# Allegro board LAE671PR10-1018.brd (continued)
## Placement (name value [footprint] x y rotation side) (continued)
CT32  0.1U_0201_6.3V6K  [C_0201]  30.03 44.23 0 bottom
CT33  0.1U_0201_6.3V6K  [C_0201]  30.03 42.7 0 bottom
CT34  0.1U_0201_6.3V6K  [C_0201]  30.03 43.34 0 bottom
CT35  0.1U_0201_6.3V6K  [C_0201]  31.79 50.88 0 bottom
CT36  0.1U_0201_6.3V6K  [C_0201]  31.79 50.25 0 bottom
CT37  27P_0201_25V8  [C_0201]  16.69 38.5 270 bottom
CT38  27P_0201_25V8  [C_0201]  16.7 39.12 90 bottom
CT39  0.22U_0201_6.3V6M  [C_0201]  15.57 45.68 180 bottom
CT40  0.22U_0201_6.3V6M  [C_0201]  13.2 49.91 135 bottom
CT41  0.22U_0201_6.3V6M  [C_0201]  15.57 45.04 180 bottom
CT42  0.22U_0201_6.3V6M  [C_0201]  12.77 49.44 135 bottom
CT43  0.22U_0201_6.3V6M  [C_0201]  15.83 43.5 180 bottom
CT44  0.22U_0201_6.3V6M  [C_0201]  11.98 48.29 135 bottom
CT45  0.22U_0201_6.3V6M  [C_0201]  15.83 44.14 180 bottom
CT46  0.22U_0201_6.3V6M  [C_0201]  12.37 48.69 135 bottom
CT47  0.1U_0201_6.3V6K  [C_0201]  31.79 44.41 0 bottom
CT48  0.1U_0201_6.3V6K  [C_0201]  30.01 41.99 0 bottom
CT49  0.1U_0201_6.3V6K  [C_0201]  31.79 43.77 0 bottom
CT50  0.1U_0201_6.3V6K  [C_0201]  30.01 41.36 0 bottom
CT51  0.1U_0201_6.3V6K  [C_0201]  15.88 64.15 45 top
CT52  1U_0201_6.3V6M  [C_0201]  26.11 48.52 0 top
CT53  1U_0201_6.3V6M  [C_0201]  26.11 47.93 0 top
CT54  1U_0201_6.3V6M  [C_0201]  22.8 47.73 270 top
CT55  1U_0201_6.3V6M  [C_0201]  23.03 50.38 0 top
CT56  1U_0201_6.3V6M  [C_0201]  26.11 46.67 0 top
CT57  1U_0201_6.3V6M  [C_0201]  26.11 47.3 0 top
CT58  1U_0201_6.3V6M  [C_0201]  25.48 46.64 270 top
CT59  0.1U_0201_10V6K  [C_0201]  25.56 50.55 0 top
CT60  1U_0201_6.3V6M  [C_0201]  21.46 51.42 0 top
CT61  1U_0201_6.3V6M  [C_0201]  16.42 52.19 270 bottom
CT62  10U_0402_6.3V6M  [C_0402]  16.42 52.97 90 bottom
CT63  10U_0402_6.3V6M  [C_0402]  15.46 53.18 90 bottom
CT64  10U_0402_6.3V6M  [C_0402]  14.59 53.18 90 bottom
CT65  10U_0402_6.3V6M  [C_0402]  13.71 53.17 90 bottom
CT66  1U_0201_6.3V6M  [C_0201]  24.88 44.28 0 top
CT67  1U_0201_6.3V6M  [C_0201]  22.97 43.44 0 top
CT68  1U_0201_6.3V6M  [C_0201]  22.97 44.02 0 top
CT69  1U_0201_6.3V6M  [C_0201]  22.36 43.44 180 top
CT70  1U_0201_6.3V6M  [C_0201]  22.36 44.02 180 top
CT71  1U_0201_6.3V6M  [C_0201]  24.88 43.69 0 top
CT72  1U_0201_6.3V6M  [C_0201]  20.87 46.57 0 top
CT73  1U_0201_6.3V6M  [C_0201]  19.64 46.29 270 top
CT74  1U_0201_6.3V6M  [C_0201]  23.4 48.53 0 top
CT75  1U_0201_6.3V6M  [C_0201]  18.96 47.92 90 top
CT76  1U_0201_6.3V6M  [C_0201]  23.39 47.93 0 top
CT77  1U_0201_6.3V6M  [C_0201]  19.05 46.3 270 top
CT78  1U_0201_6.3V6M  [C_0201]  18.46 46.3 270 top
CT79  47U_0603_6.3V  [C_0603]  15.6 56.85 180 bottom
CT80  47U_0603_6.3V  [C_0603]  15.6 55.58 180 bottom
CT81  47U_0603_6.3V  [C_0603]  15.6 58.12 180 bottom
CT82  1U_0201_6.3V6M  [C_0201]  24.96 49.79 0 top
CT83  1U_0201_6.3V6M  [C_0201]  24.3 49.19 90 top
CT84  1U_0201_6.3V6M  [C_0201]  24.68 47.89 90 top
CT85  10U_0402_6.3V6M  [C_0402]  18.69 43.67 270 top
CT86  10U_0402_6.3V6M  [C_0402]  19.57 43.67 270 top
CT87  1U_0201_6.3V6M  [C_0201]  19.72 44.41 180 top
CT88  1U_0201_6.3V6M  [C_0201]  19.72 45.04 180 top
CT89  1U_0201_6.3V6M  [C_0201]  22.26 44.66 180 top
CT90  1U_0201_6.3V6M  [C_0201]  20.99 44.66 180 top
CT91  1U_0201_6.3V6M  [C_0201]  24.68 47.11 270 top
CT92  47U_0603_6.3V  [C_0603]  26.73 58.04 180 bottom
CT93  47U_0603_6.3V  [C_0603]  26.73 56.82 180 bottom
CT94  4.7U_0402_6.3V6M  [C_0402]  15.13 35.12 90 top
CT95  4.7U_0402_6.3V6M  [C_0402]  22.98 33.46 0 top
CT96  2.2U_0402_6.3V6M  [C_0402]  20.44 34.88 90 top
CT97  4.7U_0402_6.3V6M  [C_0402]  27.68 37.43 90 top
CT98  4.7U_0402_6.3V6M  [C_0402]  34.94 37.05 0 top
CT99  2.2U_0402_6.3V6M  [C_0402]  32.98 37.12 90 top
CT100  4.7U_0402_6.3V6M  [C_0402]  283.17 21.04 0 bottom
CT101  4.7U_0402_6.3V6M  [C_0402]  294.58 13.71 0 bottom
CT102  2.2U_0402_6.3V6M  [C_0402]  283.17 14.93 180 bottom
CT103  10U_0603_25V6M  [C_0603]  8.88 40.11 270 top
CT104  10U_0603_25V6M  [C_0603]  12.49 61 270 top
CT105  1U_0402_25V6K  [C_0402]  287.05 48.27 90 bottom
CZ1  0.1U_0402_10V7K  [C_0402]  138.33 72.34 0 top
CZ2  1U_0402_6.3V6K  [C_0402]  140.43 72.35 0 top
CZ3  1U_0402_6.3V6K  [C_0402]  145.96 12.83 90 bottom
CZ4  0.1U_0402_10V7K  [C_0402]  150.37 10.95 90 bottom
CZ5  0.1U_0402_10V7K  [C_0402]  148.07 15.01 180 bottom
CZ6  0.1U_0402_10V7K  [C_0402]  125.2 41.34 270 top
CZ7  1U_0402_6.3V6K  [C_0402]  120.05 38.74 90 top
CZ8  0.1U_0402_10V7K  [C_0402]  128.31 69.68 180 top
CZ9  1U_0402_6.3V6K  [C_0402]  125.64 69.68 0 top
D2  -  [TVNST52302AB0_SOT523-3]  284.47 22.97 90 bottom
D3  -  [AZ5B25-01F_DFN0603P2Y2]  285.4 23.38 270 bottom
D4  -  [AZ5B25-01F_DFN0603P2Y2]  285.4 24.08 90 bottom
D5  -  [BAT54CW_SOT323-3]  42.01 52.03 90 bottom
D6  -  [BAT54CW_SOT323-3]  57.32 67.83 270 bottom
D7  -  [RB751V40_SC76-2]  267.86 64.74 0 top
D8  -  [RB751V40_SC76-2]  267.86 66.43 0 top
D9  -  [RB751V40_SC76-2]  271.41 64.57 90 top
D10  -  [TVNST52302AB0_SOT523-3]  272.25 57.17 180 top
D11  -  [RB751V40_SC76-2]  254.22 8.97 90 bottom
D12  -  [RB751V40_SC76-2]  201.23 7.35 90 bottom
D13  -  [BAT54CW_SOT323-3]  38.71 52.28 90 bottom
D18  AZ5B25-01F_DFN0603P2Y2  [ESD101-B1-02ELS_TSSLP-2-4-2]  49.98 58.99 0 bottom
D20  -  [TVNST52302AB0_SOT523-3]  280.52 8.97 90 bottom
D21  BAT54LPS-7  [BZT52C15LP-7_DFN1006-2-2]  13.97 22.74 180 top
D22  BAT54LPS-7  [BZT52C15LP-7_DFN1006-2-2]  26.17 26.12 180 top
D23  BAT54LPS-7  [BZT52C15LP-7_DFN1006-2-2]  294.49 12.96 180 top
D24  ESD8011MUT5G  [ESD101-B1-02ELS_TSSLP-2-4-2]  8.55 43.52 270 bottom
D25  ESD8011MUT5G  [ESD101-B1-02ELS_TSSLP-2-4-2]  9.64 43.92 225 top
D26  ESD8011MUT5G  [ESD101-B1-02ELS_TSSLP-2-4-2]  8.55 44.15 90 bottom
D27  ESD8011MUT5G  [ESD101-B1-02ELS_TSSLP-2-4-2]  10.09 44.37 45 top
D28  ESD8011MUT5G  [ESD101-B1-02ELS_TSSLP-2-4-2]  7.85 40.22 0 bottom
D29  ESD8011MUT5G  [ESD101-B1-02ELS_TSSLP-2-4-2]  7.51 37.54 0 top
D30  ESD8011MUT5G  [ESD101-B1-02ELS_TSSLP-2-4-2]  7.51 38.3 0 top
D31  ESD8011MUT5G  [ESD101-B1-02ELS_TSSLP-2-4-2]  8.6 37.73 0 top
D32  ESD8011MUT5G  [ESD101-B1-02ELS_TSSLP-2-4-2]  8.55 49.1 270 bottom
D33  ESD8011MUT5G  [ESD101-B1-02ELS_TSSLP-2-4-2]  11.58 47.51 225 top
D34  ESD8011MUT5G  [ESD101-B1-02ELS_TSSLP-2-4-2]  8.55 49.74 90 bottom
D35  ESD8011MUT5G  [ESD101-B1-02ELS_TSSLP-2-4-2]  12.03 47.96 45 top
D36  ESD8011MUT5G  [ESD101-B1-02ELS_TSSLP-2-4-2]  9.92 41.03 180 top
D37  ESD8011MUT5G  [ESD101-B1-02ELS_TSSLP-2-4-2]  9.44 46.71 225 top
D38  ESD8011MUT5G  [ESD101-B1-02ELS_TSSLP-2-4-2]  10.56 41.03 0 top
D39  ESD8011MUT5G  [ESD101-B1-02ELS_TSSLP-2-4-2]  9.89 47.16 45 top
D40  ESD8011MUT5G  [ESD101-B1-02ELS_TSSLP-2-4-2]  8.55 59.96 270 bottom
D41  ESD8011MUT5G  [ESD101-B1-02ELS_TSSLP-2-4-2]  9.13 60.02 225 top
D42  ESD8011MUT5G  [ESD101-B1-02ELS_TSSLP-2-4-2]  8.55 60.6 90 bottom
D43  ESD8011MUT5G  [ESD101-B1-02ELS_TSSLP-2-4-2]  9.67 60.56 45 top
D44  ESD8011MUT5G  [ESD101-B1-02ELS_TSSLP-2-4-2]  8.17 55.65 270 top
D45  ESD8011MUT5G  [ESD101-B1-02ELS_TSSLP-2-4-2]  8.17 57.04 270 top
D46  ESD8011MUT5G  [ESD101-B1-02ELS_TSSLP-2-4-2]  7.41 57.04 270 top
D47  ESD8011MUT5G  [ESD101-B1-02ELS_TSSLP-2-4-2]  10.26 64.35 0 top
D48  ESD8011MUT5G  [ESD101-B1-02ELS_TSSLP-2-4-2]  9.06 65.12 270 bottom
D49  ESD8011MUT5G  [ESD101-B1-02ELS_TSSLP-2-4-2]  12.14 64.69 225 top
D50  ESD8011MUT5G  [ESD101-B1-02ELS_TSSLP-2-4-2]  9.06 65.76 90 bottom
D51  ESD8011MUT5G  [ESD101-B1-02ELS_TSSLP-2-4-2]  12.68 65.23 45 top
D52  ESD8011MUT5G  [ESD101-B1-02ELS_TSSLP-2-4-2]  9.25 56.98 180 top
D53  ESD8011MUT5G  [ESD101-B1-02ELS_TSSLP-2-4-2]  9.56 62.63 270 top
D54  ESD8011MUT5G  [ESD101-B1-02ELS_TSSLP-2-4-2]  9.88 56.98 0 top
D55  ESD8011MUT5G  [ESD101-B1-02ELS_TSSLP-2-4-2]  9.56 63.39 90 top
D56  ESD8011MUT5G  [ESD101-B1-02ELS_TSSLP-2-4-2]  287.12 45.04 0 top
D57  ESD8011MUT5G  [ESD101-B1-02ELS_TSSLP-2-4-2]  288.2 46.95 0 bottom
D58  ESD8011MUT5G  [ESD101-B1-02ELS_TSSLP-2-4-2]  286.49 45.04 180 top
D59  ESD8011MUT5G  [ESD101-B1-02ELS_TSSLP-2-4-2]  287.44 46.95 180 bottom
D60  ESD8011MUT5G  [ESD101-B1-02ELS_TSSLP-2-4-2]  286.45 48.44 180 top
D61  ESD8011MUT5G  [ESD101-B1-02ELS_TSSLP-2-4-2]  277.24 25.48 0 top
D62  ESD8011MUT5G  [ESD101-B1-02ELS_TSSLP-2-4-2]  277.24 26.25 0 top
D63  ESD8011MUT5G  [ESD101-B1-02ELS_TSSLP-2-4-2]  289.55 43.59 180 bottom
D64  ESD8011MUT5G  [ESD101-B1-02ELS_TSSLP-2-4-2]  287.57 52.53 270 top
D65  ESD8011MUT5G  [ESD101-B1-02ELS_TSSLP-2-4-2]  288.51 52.53 270 bottom
D66  ESD8011MUT5G  [ESD101-B1-02ELS_TSSLP-2-4-2]  287.57 53.22 90 top
D67  ESD8011MUT5G  [ESD101-B1-02ELS_TSSLP-2-4-2]  288.51 53.17 90 bottom
D68  ESD8011MUT5G  [ESD101-B1-02ELS_TSSLP-2-4-2]  287.26 49.42 270 top
D69  ESD8011MUT5G  [ESD101-B1-02ELS_TSSLP-2-4-2]  287.26 47.02 270 top
D70  ESD8011MUT5G  [ESD101-B1-02ELS_TSSLP-2-4-2]  287.26 50.06 90 top
D71  ESD8011MUT5G  [ESD101-B1-02ELS_TSSLP-2-4-2]  287.26 47.66 90 top
D72  AZ5B25-01F_DFN0603P2Y2  [ESD101-B1-02ELS_TSSLP-2-4-2]  281.22 23.59 0 bottom
D73  -  [TVNST52302AB0_SOT523-3]  275.3 57.24 180 top
D74  -  [PESD5V0U2BT_SOT23-3]  277.38 39.43 270 bottom
D75  -  [BAT54CW_SOT323-3]  268.4 54.74 180 top
D78  BAT54LPS-7  [BZT52C15LP-7_DFN1006-2-2]  210.29 10.31 90 bottom
D79  BAT54LPS-7  [BZT52C15LP-7_DFN1006-2-2]  263.36 6.55 90 bottom
DA1  -  [ESD203-B1-02EL_TSLP-2-20-2]  283.79 12.2 90 top
DA2  -  [ESD203-B1-02EL_TSLP-2-20-2]  281.85 10.44 90 top
DA3  -  [ESD203-B1-02EL_TSLP-2-20-2]  284.72 7.48 90 top
DA4  -  [ESD203-B1-02EL_TSLP-2-20-2]  280.75 5.08 270 top
DA5  AZ5123-01F.R7G_DFN1006P2X2  [ESD207-B1-02EL_TSLP-2-19-2]  292.71 69.36 90 bottom
DA6  AZ5123-01F.R7G_DFN1006P2X2  [ESD207-B1-02EL_TSLP-2-19-2]  286.55 64.23 270 bottom
DA7  AZ5123-01F.R7G_DFN1006P2X2  [ESD207-B1-02EL_TSLP-2-19-2]  289.38 60.06 270 bottom
DA8  AZ5123-01F.R7G_DFN1006P2X2  [ESD207-B1-02EL_TSLP-2-19-2]  288.33 60.06 270 bottom
DA9  AZ5123-01F.R7G_DFN1006P2X2  [ESD207-B1-02EL_TSLP-2-19-2]  290.51 60.07 270 bottom
DI1  AZ4024-02S_SOT23-3~D  [PESD24VS2UT_SOT23-3]  20.18 25.56 270 bottom
DI2  AZ4024-02S_SOT23-3~D  [PESD24VS2UT_SOT23-3]  26.34 29.41 0 bottom
DI3  AZ4024-02S_SOT23-3~D  [PESD24VS2UT_SOT23-3]  294.02 9.1 0 top
DZ2  -  [RB751V40_SC76-2]  285.79 51.71 90 bottom
DZ3  -  [RB751V40_SC76-2]  289.54 39.72 180 bottom
FD1  FIDUCAL  [FIDUCIAL_C40M80]  294.95 69.36 180 bottom
FD2  FIDUCIAL  [FIDUCIAL_C40M80]  24.26 4.81 180 bottom
FD3  FIDUCAL  [FIDUCIAL_C40M80]  294.34 4.55 0 top
FD4  FIDUCIAL  [FIDUCIAL_C40M80]  17.37 66.29 0 top
H1  H_3P3  [H_3P3-G]  24.62 63.92 180 bottom
H2  H_3P3  [H_3P3-G]  57.63 62.42 180 bottom
H3  H_3P3  [H_3P3-G]  88.73 67.85 180 bottom
H4  H_3P3  [H_3P3-G]  88.73 42.75 180 bottom
H5  H_3P3  [H_3P3-G]  145.73 67.85 180 bottom
H6  H_3P3  [H_3P3-G]  145.73 42.75 180 bottom
H7  H_3P3  [H_3P3-G]  76.76 26.95 180 bottom
H8  H_2P6  [H_2P6-G]  169.58 47.8 180 bottom
H9  H_2P6  [H_2P6-G]  218.19 19.81 180 bottom
H10  H_2P6  [H_2P6-G]  269.95 35.75 180 bottom
H11  H_2P0  [H_2P0-G]  2.63 71.4 0 top
H12  H_2P0  [H_2P0-G]  3.43 38.85 0 top
H13  H_2P0  [H_2P0-G]  3.68 8.8 0 top
H14  -  [H_2P0N]  81.53 74.26 0 top
H16  H_2P0  [H_2P0-G]  294.63 58.25 0 top
H17  H_2P0  [H_2P0-G]  294.11 22.2 0 top
H18  -  [H_2P0N]  148.63 74.26 0 top
H19  H_1P8  [H_1P8-G]  147.57 6.77 0 top
H20  H_1P8  [H_1P8-G]  214.24 8.38 0 top
H21  H_2P0  [H_2P0-G]  3.93 54.94 0 top
H22  -  [H_1P8N]  10.8 66.9 0 top
H23  H_2P0  [H_2P0-G]  293.38 42.15 0 top
H24  -  [CLIP_C6-PM]  167.73 20.5 180 bottom
H25  -  [H_1P2X1P7N]  285.04 66.9 270 bottom
H26  -  [H_1P8X2P3N]  7.49 19.04 0 top
JAPS1  ACES_50506-01841-P01  [ACES_50506-01841-P01_18P]  160.57 27.71 90 top
JAUDIO1  HRS_BM20B(0P8)10DS0P4V(51)  [HRS_BM20B0P810DS0P4V51_10P-T]  291.82 62.6 0 bottom
JCAM1  ACES_50406-02071-001  [ACES_50406-02071-001_20P]  278.8 28.44 270 bottom
JCR1  T-SOL_158-1160902600  [T-SOL_158-1090902600_18P-T]  283.01 34.94 90 top
JDEG1  JXT_FP225H-010G1AM  [JXT_FP225H-010G1AM_10P]  16.3 11.54 0 bottom
JEDP1  EDP  [ACES_50398-04041-001_40P]  51.08 61.8 180 bottom
JESPI1  JXT_FP225H-010G1AM  [JXT_FP225H-010G1AM_10P]  10.77 5.62 90 bottom
JFAN1  ACES_50224-00401-001  [ACES_50224-00401-001_4P]  257.15 5.35 0 bottom
JFAN2  ACES_50224-00401-001  [ACES_50224-00401-001_4P]  204.83 1.82 0 bottom
JFP2  ACES_50521-00841-P01  [ACES_50521-00841-P01_8P-T]  276.08 7.03 180 bottom
JKB1  E-T_6710K-Y15M-31L  [E-T_6710K-Y15M-31L_15P]  21.18 9.59 180 bottom
JNGFF1  LOTES_APCI0146-P004A  [LOTES_APCI0146-P004A_75P]  160.28 17.7 90 bottom
JP2  PAD-OPEN1X1M  [JUMP_43X39]  21.63 23.58 270 top
JP3  PAD-OPEN1X1M  [JUMP_43X39]  23.92 23.53 270 top
JPA1  -  [JUMP_43X39]  278.2 58.55 180 top
JPA2  -  [JUMP_43X39]  288.56 57.73 0 bottom
JRTC1  ACES_50278-00201-001  [ACES_50278-00201-001_2P]  252.88 5.47 90 bottom
JSPI1  ACES_50696-0200M-P01  [ACES_50696-0200M-P01_20P]  163.6 27.28 270 bottom
JSPK1  ACES_50208-00801-003  [ACES_50208-00801-003_8P]  282.76 4.89 270 bottom
JT101  ACES_50278-01201-001  [ACES_50278-01201-001_12P-T]  108.44 14.61 180 bottom
JTAG2  @SHORT PADS~D  [SHORTPADS]  9.09 13.02 180 top
JTP1  ACES_50506-00841-P01  [ACES_50506-00841-P01_8P]  178.58 8.25 180 bottom
JUART1  CVILU_CI1804M1VRA-NH  [CVILU_CI1804M1VRA-NH_4P]  162.79 42.08 270 top
JUSBC1  JAE_DX07SD24JJ3  [JAE_DX07SD24JJ3_24P-T]  7.4 49.34 270 top
JUSBC2  JAE_DX07SD24JJ3  [JAE_DX07SD24JJ3_24P-T]  7.4 65.8 270 top
JUSBC3  JAE_DX07SA24XJ2  [JAE_DX07SA24XJ2_24P-T]  289.2 47.55 90 top
JXDP1  E-T_6601K-Y61N-04L  [E-T_6601K-Y61N-04L_61P]  53.08 73.31 180 top
L1  EXC24CH900U_4P  [INPAQ_MCM1012B900F06BP_4P]  287.61 23.98 180 bottom
L2  EXC24CH900U_4P  [INPAQ_MCM1012B900F06BP_4P]  276.72 35.63 90 bottom
LA1  BLM15PX600SN1D_2P  [MURAT_BLM15PX600SN1D_2P]  274.23 55.75 270 top
LA2  BLM15BB220SN1D_2P  [MURAT_BLM15BB220SN1D_2P]  268.85 62.38 270 bottom
LA3  HCB1005KF-600T25_2P  [TAI-T_HCB1005KF-600T25_2P]  278.64 56.47 180 top
LA4  BLM15BB220SN1D_2P  [MURAT_BLM15BB220SN1D_2P]  273.88 63.89 90 top
LA5  BLM15PX121SN1D_2P  [MURAT_BLM15PX181SN1D_2P]  278.39 11.85 0 top
LA6  BLM15PX121SN1D_2P  [MURAT_BLM15PX181SN1D_2P]  279.26 10.12 0 top
LA7  BLM15PX121SN1D_2P  [MURAT_BLM15PX181SN1D_2P]  279.23 7.68 0 top
LA8  BLM15PX121SN1D_2P  [MURAT_BLM15PX181SN1D_2P]  278.18 5.35 0 top
LA9  BLM15PX330SN1D_2P  [MURAT_BLM15PX330SN1D_2P]  287.36 59.45 180 bottom
LA10  BLM15PX330SN1D_2P  [MURAT_BLM15PX330SN1D_2P]  285.68 61.22 0 bottom
LA11  BLM15PX600SN1D_2P  [MURAT_BLM15PX600SN1D_2P]  266.53 29.2 180 top
LED1  27-11-T1D-CP1Q1RY-3C_WHITE~D  [LED_27-11-T1D-CP1Q1RY-3C_2P]  2.63 27.3 90 top
LED2  27-11-T1D-CP1Q1RY-3C_WHITE~D  [LED_27-11-T1D-CP1Q1RY-3C_2P]  2.63 23.7 90 top
LED3  27-11-T1D-CP1Q1RY-3C_WHITE~D  [LED_27-11-T1D-CP1Q1RY-3C_2P]  2.63 20.1 90 top
LED4  27-11-T1D-CP1Q1RY-3C_WHITE~D  [LED_27-11-T1D-CP1Q1RY-3C_2P]  2.63 16.5 90 top
LED5  27-11-T1D-CP1Q1RY-3C_WHITE~D  [LED_27-11-T1D-CP1Q1RY-3C_2P]  2.63 12.9 90 top
LED6  HT-F196BP5_WHITE  [LED_HT-F196BP5_2P]  290.9 70.69 0 top
LT1  0.60UH +-20% MND-04ABIR60M-XGL  [COILC_XFL4012-601MEC_2P]  18.33 55.36 90 bottom
LT2  LQM18PN1R0MFHD_2P  [CHILI_PBY160808T-300Y-N_2P]  28.19 57.8 270 bottom
LT3  HCB2012KF-121T50_0805  [TAI-T_HCB2012KF-121T50_2P]  15.48 24.66 270 top
LT4  HCB2012KF-121T50_0805  [TAI-T_HCB2012KF-121T50_2P]  29.38 28.26 270 bottom
LT5  HCB2012KF-121T50_0805  [TAI-T_HCB2012KF-121T50_2P]  293.24 15.71 0 top
LT6  HCB2012KF-121T50_0805  [TAI-T_HCB2012KF-121T50_2P]  265.21 4.88 180 bottom
LT7  HCB2012KF-121T50_0805  [TAI-T_HCB2012KF-121T50_2P]  212.34 2.05 180 bottom
MC1  680P_0402_50V7K~D  [C_0402]  55.36 67.12 90 bottom
MD1  -  [PESD5V0U2BT_SOT23-3]  171.26 8.08 270 bottom
MD2  -  [PESD5V0U2BT_SOT23-3]  169.71 2.6 180 bottom
MD3  -  [PESD5V0U2BT_SOT23-3]  272.61 7.28 0 bottom
ML1  EXC24CH900U_4P  [INPAQ_MCM1012B900F06BP_4P]  279.27 12.86 270 bottom
ML2  EXC24CH900U_4P  [INPAQ_MCM1012B900F06BP_4P]  11.19 45.18 135 top
ML3  EXC24CH900U_4P  [INPAQ_MCM1012B900F06BP_4P]  10.14 38.48 90 top
ML4  EXC24CH900U_4P  [INPAQ_MCM1012B900F06BP_4P]  11.74 62.75 180 top
ML5  EXC24CH900U_4P  [INPAQ_MCM1012B900F06BP_4P]  9.34 54.79 90 top
ML6  EXC24CH900U_4P  [INPAQ_MCM1012B900F06BP_4P]  285 50 0 top
ML7  EXC24CH900U_4P  [INPAQ_MCM1012B900F06BP_4P]  284.86 47.42 0 top
NOREF  -  []  145.73 42.75 0 top
NOREF#2  -  []  88.73 67.85 0 top
NOREF#3  -  []  81.65 38.23 270 top
NOREF#4  -  []  81.53 74.26 0 top
NOREF#5  -  []  269.95 35.75 0 top
NOREF#6  -  []  88.73 67.85 0 top
NOREF#7  -  []  293.38 42.15 0 top
NOREF#8  -  []  214.24 8.38 0 top
NOREF#9  -  []  88.73 42.75 0 top
NOREF#10  -  []  57.63 62.42 0 top
NOREF#11  -  []  269.95 35.75 0 top
NOREF#12  -  []  76.77 26.96 0 top
NOREF#13  -  []  24.62 63.92 0 top
NOREF#14  -  []  24.62 63.92 0 top
NOREF#15  -  []  145.73 67.85 0 top
NOREF#16  -  []  2.63 71.4 0 top
NOREF#17  -  []  153.71 8.45 0 top
NOREF#18  -  []  3.68 8.8 0 top
NOREF#19  -  []  88.73 42.75 0 top
NOREF#20  -  []  269.95 35.75 0 top
NOREF#21  -  []  3.93 54.94 0 top
NOREF#22  -  []  77.58 8.34 0 top
NOREF#23  -  []  57.63 62.42 0 top
NOREF#24  -  []  3.43 38.85 0 top
NOREF#25  -  []  148.63 77.68 0 top
NOREF#26  -  []  148.63 74.26 0 top
NOREF#27  -  []  169.58 47.8 0 top
NOREF#28  -  []  41.3 -33.23 0 top
NOREF#29  -  []  107.02 8.36 0 top
NOREF#30  -  []  145.73 67.85 0 top
NOREF#31  -  []  147.57 6.77 0 top
NOREF#32  -  []  145.73 42.75 0 top
NOREF#33  -  []  108.11 2.53 0 top
NOREF#34  -  []  294.63 58.25 0 top
NOREF#35  -  []  294.11 22.2 0 top
NOREF#36  -  []  218.19 19.81 0 top
NOREF#37  -  []  61.55 70.57 0 top
NOREF#38  -  []  111.07 30.33 180 bottom
NOREF#39  -  []  35.68 55.76 180 bottom
NOREF#40  -  []  139.63 34.84 180 bottom
PC100  2200P_0402_50V7K  [C_0402]  32.08 21.34 180 bottom
PC101  0.1U_0402_25V6  [C_0402]  34.25 22.69 90 top
PC102  100P_0402_50V8J  [C_0402]  32.08 22.21 180 bottom
PC103  0.01U_0402_25V7K  [C_0402]  33.31 22.67 90 top
PC104  1000P_0402_50V7K  [C_0402]  38.61 20.16 90 top
PC105  100P_0402_50V8J  [C_0402]  37.75 20.18 90 top
PC106  0.1U_0402_25V6  [C_0402]  39.29 20.16 90 bottom
PC107  1U_0603_25V6K  [C_0603]  39.21 18.82 270 top
PC108  2200P_0402_50V7K  [C_0402]  38.36 20.16 90 bottom
PC109  0.22U_0402_25V6K  [C_0402]  34.41 16.97 180 top
PC111  680P_0402_50V7K  [C_0402]  39.61 4.53 180 top
PC114  100P_0402_50V8J  [C_0402]  45.9 21.6 0 bottom
PC115  1U_0603_25V6K  [C_0603]  40.87 18.84 270 bottom
PC116  0.1U_0402_25V6  [C_0402]  45.89 20.71 0 bottom
PC117  2200P_0402_50V7K  [C_0402]  40.42 20.19 90 bottom
PC118  100P_0402_50V8J  [C_0402]  41.37 20.2 90 top
PC119  1000P_0402_50V7K  [C_0402]  41.37 20.2 90 bottom
PC120  2200P_0402_50V7K  [C_0402]  45.9 20.7 0 top
PC121  0.1U_0402_25V6  [C_0402]  40.42 20.19 90 top
PC122  0.01U_0402_25V7K  [C_0402]  45.9 21.6 0 top
PC123  0.22U_0402_25V6K  [C_0402]  43.04 18.88 270 top
PC124  680P_0402_50V7K  [C_0402]  46.9 8.72 270 top
PC125  0.01U_0402_16V7K  [C_0402]  45.94 3.32 270 top
PC126  1000P_0402_50V7K  [C_0402]  96.77 9.97 270 top
PC127  0.01U_0402_25V7K  [C_0402]  84.67 10.13 180 bottom
PC128  1U_0603_25V6K  [C_0603]  35.33 2.47 90 bottom
PC129  1U_0402_16V6K  [C_0402]  40.62 2.64 270 bottom
PC130  0.1U_0402_25V6  [C_0402]  53 2.67 90 top
PC131  1U_0603_25V6K  [C_0603]  36.36 1.8 90 top
PC132  2200P_0402_50V7K  [C_0402]  95.63 9.05 90 top
PC133  10U_0603_25V6M  [C_0603]  39.21 18.83 270 bottom
PC134  10U_0603_25V6M  [C_0603]  40.87 18.82 270 top
PC136  1000P_0402_50V7K  [C_0402]  32.25 20.15 180 top
PC137  1000P_0402_50V7K  [C_0402]  49.2 15.28 0 top
PC140  1000P_0402_50V7K  [C_0402]  51.6 17.93 270 bottom
PC283  100P_0402_50V8J  [C_0402]  197.29 8.47 90 bottom
PC284  0.1U_0402_25V6  [C_0402]  200.83 4.54 270 bottom
PC285  1U_0603_25V6K  [C_0603]  198.33 8.03 90 bottom
PC286  0.22U_0402_25V6K  [C_0402]  194.63 6.23 270 bottom
PC287  1000P_0402_50V7K  [C_0402]  193.4 2.71 0 bottom
PC288  1000P_0402_50V7K  [C_0402]  195.51 8.44 90 bottom
PC289  0.01U_0402_25V7K  [C_0402]  199.95 4.54 270 bottom
PC290  2200P_0402_50V7K  [C_0402]  194.63 8.45 90 bottom
PC291  680P_0402_50V7K  [C_0402]  183.4 6.97 90 bottom
PC292  100P_0402_50V8J  [C_0402]  202.29 5.51 90 bottom
PC293  0.1U_0402_25V6  [C_0402]  196.4 8.46 90 bottom
PC294  2200P_0402_50V7K  [C_0402]  201.41 5.53 90 bottom
PC295  10U_0603_25V6M  [C_0603]  198.73 4.78 180 bottom
PC301  0.1U_0402_25V6  [C_0402]  55.15 10.26 0 bottom
PC302  10U_0603_25V6M  [C_0603]  57.24 20.85 180 bottom
PC303  0.1U_0402_25V6  [C_0402]  56.77 18.64 180 top
PC304  10U_0603_25V6M  [C_0603]  57.23 23.65 180 top
PC305  10U_0603_25V6M  [C_0603]  57.24 20.85 180 top
PC306  2200P_0402_50V7K  [C_0402]  56.77 19.59 180 top
PC307  10U_0603_25V6M  [C_0603]  57.23 22.26 180 top
PC308  10U_0603_25V6M  [C_0603]  57.23 23.65 180 bottom
PC309  10U_0603_25V6M  [C_0603]  57.23 22.26 180 bottom
PC310  10U_0603_25V6M  [C_0603]  57.22 25.05 180 bottom
PC312  4.7U_0603_25V6K  [C_0603]  62.38 16.78 0 top
PC313  1U_0402_25V6K  [C_0402]  62.4 18.75 270 bottom
PC314  1U_0402_25V6K  [C_0402]  63.79 17.84 90 bottom
PC315  10U_0603_25V6M  [C_0603]  74.33 9.39 0 bottom
PC316  10U_0603_25V6M  [C_0603]  74.3 10.83 0 bottom
PC317  10U_0603_25V6M  [C_0603]  71.82 15.53 180 top
PC318  10U_0603_25V6M  [C_0603]  71.86 12.86 180 bottom
PC319  10U_0603_25V6M  [C_0603]  71.86 12.86 180 top
PC320  10U_0603_25V6M  [C_0603]  71.82 15.53 180 bottom
PC321  0.1U_0402_25V6  [C_0402]  74.58 8.19 0 bottom
PC322  10U_0603_25V6M  [C_0603]  78.42 10.84 180 top
PC323  10U_0603_25V6M  [C_0603]  78.42 10.84 180 bottom
PC324  10U_0603_25V6M  [C_0603]  74.33 9.39 0 top
PC325  10U_0603_25V6M  [C_0603]  71.83 14.22 180 bottom
PC326  10U_0603_25V6M  [C_0603]  74.3 10.83 0 top
PC329  2200P_0402_50V7K  [C_0402]  74.58 8.19 0 top
PC330  0.22U_0603_25V7K  [C_0603]  66.18 17.97 270 top
PC331  0.1U_0402_25V6  [C_0402]  59.93 12.63 270 top
PC332  1U_0603_25V6K  [C_0603]  59.86 16.72 0 top
PC333  1U_0603_25V6K  [C_0603]  64.4 14.35 180 bottom
PC334  1U_0402_6.3V6K  [C_0402]  67.33 15.35 0 top
PC335  1U_0402_6.3V6K  [C_0402]  59.24 13.49 0 top
PC336  0.22U_0603_25V7K  [C_0603]  68.11 13.41 270 bottom
PC337  0.1U_0402_25V6  [C_0402]  64.94 2.51 180 bottom
PC339  4700P_0402_25V7K  [C_0402]  67.46 8.4 0 top
PC340  2200P_0402_50V7K  [C_0402]  84.65 11.06 180 bottom
PC341  0.1U_0402_25V6  [C_0402]  70.02 7.83 270 bottom
PC342  680P_0402_50V7K  [C_0402]  62.05 26.3 180 top
PC343  680P_0402_50V7K  [C_0402]  67.97 22.51 270 top
PC345  1U_0402_25V6K  [C_0402]  70.14 11.09 180 top
PC346  4.7U_0603_25V6K  [C_0603]  68.16 11.07 270 top
PC347  1U_0402_25V6K  [C_0402]  69.24 8.42 0 top
PC348  560P_0402_50V7K  [C_0402]  64.17 8.06 270 top
PC349  0.01U_0402_16V7K  [C_0402]  64.24 6.26 270 top
PC350  0.1U_0402_25V6  [C_0402]  14.44 5.04 0 top
PC351  0.1U_0402_25V6  [C_0402]  67.46 7.51 0 top
PC352  10P_0402_50V8J  [C_0402]  61.46 8.08 270 top
PC500  0.1U_0402_25V6  [C_0402]  52.92 23.86 180 top
PC501  2200P_0402_50V7K  [C_0402]  52.92 23.87 180 bottom
PC502  10U_0603_25V6M  [C_0603]  52.96 22.77 180 top
PC503  10U_0603_25V6M  [C_0603]  52.96 22.83 180 bottom
PC504  0.1U_0603_25V7K  [C_0603]  55.27 29.19 180 bottom
PC505  22U_0603_6.3V6M  [C_0603]  54.35 35.99 270 bottom
PC506  22U_0603_6.3V6M  [C_0603]  47.36 36.47 270 top
PC507  22U_0603_6.3V6M  [C_0603]  47.36 36.47 270 bottom
PC508  22U_0603_6.3V6M  [C_0603]  53.47 37.9 0 bottom
PC509  4.7U_0603_6.3V6M  [C_0603]  47.86 28.75 180 bottom
PC510  680P_0603_50V7K  [C_0603]  49.72 30.25 270 top
PC511  1000P_0402_25V8J  [C_0402]  47.77 25.93 180 bottom
PC512  0.1U_0603_25V7K  [C_0603]  43.09 29.86 90 top
PC513  0.1U_0402_25V6  [C_0402]  45.48 26.55 90 bottom
PC514  2200P_0402_50V7K  [C_0402]  45.48 26.55 90 top
PC515  10U_0603_25V6M  [C_0603]  44.15 22.14 180 top
PC516  10U_0603_25V6M  [C_0603]  44.12 23.37 180 top
PC517  4.7U_0603_6.3V6M  [C_0603]  38.84 29.58 90 bottom
PC518  22U_0603_6.3V6M  [C_0603]  40.35 37.33 180 top
PC519  22U_0603_6.3V6M  [C_0603]  38.94 34.88 180 bottom
PC520  22U_0603_6.3V6M  [C_0603]  38.95 36.13 180 bottom
PC521  22U_0603_6.3V6M  [C_0603]  38.96 37.33 180 bottom
PC522  22U_0603_6.3V6M  [C_0603]  38.99 38.55 180 bottom
PC523  4.7U_0603_6.3V6M  [C_0603]  37.6 29.59 90 bottom
PC524  680P_0603_50V7K  [C_0603]  38.76 29.7 0 top
PC525  1000P_0402_25V8J  [C_0402]  36.85 25.84 180 bottom
PC526  22U_0603_6.3V6M  [C_0603]  54.35 35.99 270 top
PC527  22U_0603_6.3V6M  [C_0603]  40.34 34.88 180 top
PC528  10U_0603_25V6M  [C_0603]  44.15 22.14 180 bottom
PC529  10U_0603_25V6M  [C_0603]  44.12 23.36 180 bottom
PC600  10U_0603_25V6M  [C_0603]  114.56 6.77 90 top
PC601  10U_0603_25V6M  [C_0603]  114.57 6.75 90 bottom
PC602  0.1U_0402_25V6  [C_0402]  113.49 6.7 90 top
PC603  2200P_0402_25V7K  [C_0402]  113.48 6.71 90 bottom
PC604  680P_0402_50V7K  [C_0402]  126.99 2.75 0 bottom
PC605  .1U_0402_16V7K  [C_0402]  121.43 3.3 270 bottom
PC606  1U_0402_6.3V6K  [C_0402]  120.05 3.29 270 bottom
PC607  2.2U_0402_6.3V6M  [C_0402]  119.18 3.29 270 bottom
PC608  22U_0603_6.3V6M  [C_0603]  120.84 9.29 90 bottom
PC609  330P_0402_50V7K  [C_0402]  117.18 2.35 90 bottom
PC610  22U_0603_6.3V6M  [C_0603]  126.47 10.75 180 top
PC611  22U_0603_6.3V6M  [C_0603]  126.47 9.48 180 top
PC612  22U_0603_6.3V6M  [C_0603]  126.49 10.27 180 bottom
PC613  22U_0603_6.3V6M  [C_0603]  126.47 11.69 180 bottom
PC614  1U_0402_10V6K  [C_0402]  116.37 9.05 90 bottom
PC615  22U_0603_6.3V6M  [C_0603]  118.88 9.33 180 bottom
PC616  22U_0603_6.3V6M  [C_0603]  118.86 10.53 180 bottom
PC617  0.1U_0402_10V7K  [C_0402]  115.25 9.03 90 bottom
PC618  0.1U_0402_10V7K  [C_0402]  116.15 10.78 90 bottom
PC700  680P_0603_50V7K  [C_0603]  135.61 4.91 180 top
PC701  2200P_0402_50V7K  [C_0402]  130.62 4.06 90 bottom
PC702  0.1U_0402_25V6  [C_0402]  129.75 4.06 90 bottom
PC703  0.1U_0201_10V6K  [C_0201]  137.43 2.25 90 bottom
PC704  10U_0603_25V6M  [C_0603]  131.66 5.1 90 bottom
PC705  10U_0603_25V6M  [C_0603]  131.66 5.1 90 top
PC706  330P_0402_50V7K  [C_0402]  136.82 10.52 180 bottom
PC707  22U_0603_6.3V6M  [C_0603]  141.44 11.6 90 bottom
PC708  22U_0603_6.3V6M  [C_0603]  141.22 10.91 270 top
PC709  22U_0603_6.3V6M  [C_0603]  140.23 11.6 90 bottom
PC710  22U_0603_6.3V6M  [C_0603]  142.43 10.91 270 top
PC711  2.2U_0402_6.3V6M  [C_0402]  136.77 8.74 90 bottom
PC712  0.1U_0402_25V6  [C_0402]  130.88 8.37 270 bottom
PC713  1U_0402_6.3V6K  [C_0402]  135.88 8.75 90 bottom
PC800  0.1U_0402_25V6  [C_0402]  162.13 59.12 180 bottom
PC801  22P_0402_50V8J  [C_0402]  154.9 63.29 0 bottom
PC802  22U_0603_6.3V6M  [C_0603]  157.93 58.8 0 bottom
PC803  0.1U_0402_25V6  [C_0402]  163.5 62.64 90 bottom
PC804  2200P_0402_50V7K  [C_0402]  162.59 62.63 90 bottom
PC805  10U_0603_25V6M  [C_0603]  164.56 62.39 90 bottom
PC806  3300P_0402_50V7-K  [C_0402]  161.69 65 0 bottom
PC807  680P_0402_50V7K  [C_0402]  152.19 60.84 90 bottom
PC808  10U_0603_25V6M  [C_0603]  165.82 62.38 90 bottom
PC809  22U_0603_6.3V6M  [C_0603]  157.99 57.56 0 bottom
PC900  0.1U_0402_25V6  [C_0402]  152.05 2.6 270 bottom
PC901  22P_0402_50V8J  [C_0402]  160.79 7.31 180 bottom
PC902  22U_0603_6.3V6M  [C_0603]  153.6 7.67 270 bottom
PC903  0.1U_0402_25V6  [C_0402]  155.12 2.6 270 bottom
PC904  2200P_0402_50V7K  [C_0402]  156.23 2.6 270 bottom
PC905  10U_0805_25V6K  [C_0805]  153.48 2.87 90 bottom
PC906  3300P_0402_50V7-K  [C_0402]  159.83 4.07 0 bottom
PC907  680P_0402_50V7K  [C_0402]  158.15 14.18 270 bottom
PC908  22U_0603_6.3V6M  [C_0603]  153.21 12.55 180 bottom
PC1000  4700P_0402_25V7K  [C_0402]  36.51 42.04 90 top
PC1001  0.1U_0402_10V7K  [C_0402]  33.54 45.19 0 top
PC1002  1U_0402_16V6K  [C_0402]  36.21 48.73 180 top
PC1003  0.22U_0603_16V7K  [C_0603]  36.16 49.79 180 top
PC1004  330P_0402_50V7K  [C_0402]  37.41 42.06 90 top
PC1005  1000P_0402_50V7K  [C_0402]  38.29 42.04 90 bottom
PC1006  47P_0402_50V8J  [C_0402]  39.19 42.05 90 top
PC1007  8200P_0402_25V7K  [C_0402]  39.21 40.32 90 bottom
PC1008  820P_0402_25V7  [C_0402]  41.29 38.46 90 top
PC1009  680P_0402_50V7K  [C_0402]  39.18 39.4 0 top
PC1010  2200P_0402_50V7K  [C_0402]  38.82 52.82 90 top
PC1011  .1U_0402_16V7K  [C_0402]  39.71 54.57 90 top
PC1012  0.033U_0402_16V7K  [C_0402]  37.05 54.57 90 top
PC1013  0.01UF_0402_25V7K  [C_0402]  37.94 54.57 90 top
PC1014  0.01UF_0402_25V7K  [C_0402]  40.39 42.97 270 top
PC1015  470P_0402_50V7K  [C_0402]  42.66 53.75 270 top
PC1016  0.01UF_0402_25V7K  [C_0402]  40.74 52.84 90 top
PC1017  0.047U_0402_25V7K  [C_0402]  41.26 42.98 270 bottom
PC1018  0.047U_0402_25V7K  [C_0402]  41.26 42.98 270 top
PC1019  2200P_0402_50V7K  [C_0402]  42.99 42.98 0 bottom
PC1020  330P_0402_50V7K  [C_0402]  43.73 52.86 90 top
PC1021  68P_0402_50V8J  [C_0402]  43.73 54.64 90 top
PC1022  680P_0402_50V7K  [C_0402]  40.88 55.66 0 top
PC1023  8200P_0402_25V7K  [C_0402]  45.51 55.58 180 top
PC1024  .1U_0402_16V7K  [C_0402]  42.18 39.4 270 top
PC1026  0.022U_0402_25V7K  [C_0402]  43.88 42.04 90 top
PC1027  0.022U_0402_25V7K  [C_0402]  46.07 50.42 0 top
PC1028  0.022U_0402_25V7K  [C_0402]  46.08 49.54 0 top
PC1029  0.022U_0402_25V7K  [C_0402]  42.99 42.07 90 top
PC1030  .1U_0402_16V7K  [C_0402]  48.81 47.17 0 bottom
PC1031  0.047U_0402_25V7K  [C_0402]  48.78 49.84 0 bottom
PC1032  0.047U_0402_25V7K  [C_0402]  48.81 48.05 0 bottom
PC1033  2200P_0402_50V7K  [C_0402]  46.06 50.43 0 bottom
PC1034  1500P_0402_50V7K  [C_0402]  47.87 48.39 270 bottom
PC1035  330P_0402_50V7K  [C_0402]  45.56 44.81 270 bottom
PC1036  0.01UF_0402_25V7K  [C_0402]  46.07 48.44 0 top
PC1037  68P_0402_50V8J  [C_0402]  46.93 45.93 0 bottom
PC1038  680P_0402_50V7K  [C_0402]  47.82 47.81 0 top
PC1039  2200P_0402_50V7K  [C_0402]  49.27 44.85 270 bottom
PC1100  4.7U_0603_10V6K  [C_0603]  62.35 55.78 90 bottom
PC1101  0.1U_0402_25V7K  [C_0402]  62.93 63.37 180 bottom
PC1102  100U_D_20VM_R55M  [C_D]  64.85 72.49 0 bottom
PC1103  100U_D_20VM_R55M  [C_D]  59.77 40.07 90 bottom
PC1104  10U_0603_25V6M  [C_0603]  64.96 48.52 0 top
PC1105  10U_0603_25V6M  [C_0603]  65.2 45.06 0 top
PC1106  0.1U_0402_25V6  [C_0402]  67.67 64.48 0 top
PC1107  2200P_0402_50V7K  [C_0402]  67.66 65.37 0 top
PC1108  100U_D2_16VM_R50M  [C_D2]  64.85 67.81 0 bottom
PC1109  47P_0603_50V8J  [C_0603]  70.44 64.12 90 top
PC1110  4.7U_0603_10V6K  [C_0603]  62.86 46.08 90 bottom
PC1111  0.1U_0402_25V7K  [C_0402]  62.12 51.7 180 bottom
PC1112  10U_0603_25V6M  [C_0603]  64.9 53.77 0 bottom
PC1113  10U_0603_25V6M  [C_0603]  64.9 53.77 0 top
PC1114  0.1U_0402_25V6  [C_0402]  65.06 54.81 0 top
PC1115  2200P_0402_50V7K  [C_0402]  65.34 57.26 0 top
PC1116  47P_0603_50V8J  [C_0603]  68.42 53.2 90 top
PC1117  33U_B3_16VM_R45M  [C_B3]  64.58 56.14 0 bottom
PC1118  33U_B3_16VM_R45M  [C_B3]  64.97 46.49 0 bottom
PC1119  10U_0603_25V6M  [C_0603]  63.77 53.78 180 bottom
PC1120  10U_0603_25V6M  [C_0603]  65.47 64.78 0 bottom
PC1121  10U_0603_25V6M  [C_0603]  63.79 64.41 180 bottom
PC1150  4.7U_0603_10V6K  [C_0603]  66.77 40.53 180 top
PC1151  0.1U_0402_25V7K  [C_0402]  62.87 44.37 270 bottom
PC1152  10U_0603_25V6M  [C_0603]  64.78 63.49 0 bottom
PC1153  10U_0603_25V6M  [C_0603]  64.78 63.49 0 top
PC1154  0.1U_0402_25V6  [C_0402]  65.01 47.22 0 top
PC1155  2200P_0402_50V7K  [C_0402]  65.01 46.23 0 top
PC1156  680P_0603_50V7K  [C_0603]  70.75 39.78 180 top
PC1157  10U_0603_25V6M  [C_0603]  65.55 39.11 0 bottom
PC1158  10U_0603_25V6M  [C_0603]  65.55 39.11 0 top
PC1159  0.1U_0402_25V6  [C_0402]  50.71 48.67 90 bottom
PC1160  2200P_0402_50V7K  [C_0402]  58.16 49.51 90 bottom
PC1161  10U_0603_25V6M  [C_0603]  59.32 49.55 90 bottom
PC1162  10U_0603_25V6M  [C_0603]  51.76 48.55 90 bottom
PC1163  10U_0603_25V6M  [C_0603]  51.76 48.55 90 top
PC1164  4.7U_0603_6.3V6M  [C_0603]  59.62 48.43 180 bottom
PC1165  0.1U_0603_25V7K  [C_0603]  55.53 45.04 0 bottom
PC1166  680P_0603_50V7K  [C_0603]  55.03 53.02 270 top
PC1200  22U_0603_6.3V6M  [C_0603]  80.2 66.09 90 top
PC1201  22U_0603_6.3V6M  [C_0603]  114.77 59.18 270 top
PC1202  22U_0603_6.3V6M  [C_0603]  115.99 59.18 270 top
PC1203  22U_0603_6.3V6M  [C_0603]  81.41 66.09 90 top
PC1204  22U_0603_6.3V6M  [C_0603]  118.43 59.18 270 top
PC1205  22U_0603_6.3V6M  [C_0603]  93.09 61.88 90 bottom
PC1206  22U_0603_6.3V6M  [C_0603]  82.61 65.44 90 top
PC1207  22U_0603_6.3V6M  [C_0603]  81.82 60.04 270 top
PC1208  22U_0603_6.3V6M  [C_0603]  78.97 66.08 90 top
PC1209  22U_0603_6.3V6M  [C_0603]  85.45 60.03 270 top
PC1210  22U_0603_6.3V6M  [C_0603]  74.82 65.77 90 top
PC1211  22U_0603_6.3V6M  [C_0603]  85.74 61.89 90 bottom
PC1212  22U_0603_6.3V6M  [C_0603]  114.39 55.97 0 top
PC1213  22U_0603_6.3V6M  [C_0603]  73.46 65.79 90 bottom
PC1214  22U_0603_6.3V6M  [C_0603]  117.21 59.18 270 top
PC1215  22U_0603_6.3V6M  [C_0603]  74.82 65.77 90 bottom
PC1216  22U_0603_6.3V6M  [C_0603]  79.29 57.11 270 bottom
PC1217  22U_0603_6.3V6M  [C_0603]  100.74 55.72 90 top
PC1218  22U_0603_6.3V6M  [C_0603]  95.07 54.29 270 top
PC1219  22U_0603_6.3V6M  [C_0603]  96.8 55.72 90 top
PC1220  22U_0603_6.3V6M  [C_0603]  105.18 59.02 270 top
PC1221  22U_0603_6.3V6M  [C_0603]  90.47 48.74 270 bottom
PC1222  22U_0603_6.3V6M  [C_0603]  108.02 65.98 180 top
PC1223  22U_0603_6.3V6M  [C_0603]  98.71 55.72 90 top
PC1224  22U_0603_6.3V6M  [C_0603]  89.64 58.88 90 top
PC1225  22U_0603_6.3V6M  [C_0603]  96.28 54.3 270 top
PC1226  22U_0603_6.3V6M  [C_0603]  91.88 61.89 90 bottom
PC1227  22U_0603_6.3V6M  [C_0603]  98.71 54.32 270 top
PC1228  22U_0603_6.3V6M  [C_0603]  97.48 54.3 270 top
PC1229  22U_0603_6.3V6M  [C_0603]  104.51 52.6 90 top
PC1230  22U_0603_6.3V6M  [C_0603]  76.43 65.76 90 top
PC1231  22U_0603_6.3V6M  [C_0603]  83.86 65.44 90 bottom
PC1232  22U_0603_6.3V6M  [C_0603]  118.26 53.37 90 top
PC1233  22U_0603_6.3V6M  [C_0603]  118.33 55.97 180 top
PC1234  22U_0603_6.3V6M  [C_0603]  116.99 53.37 90 top
PC1235  22U_0603_6.3V6M  [C_0603]  115.72 53.37 90 top
PC1236  22U_0603_6.3V6M  [C_0603]  78.08 57.1 270 top
PC1237  22U_0603_6.3V6M  [C_0603]  76.87 57.09 270 top
PC1238  22U_0603_6.3V6M  [C_0603]  79.29 57.11 270 top
PC1239  22U_0603_6.3V6M  [C_0603]  114.45 53.37 90 top
PC1240  22U_0603_6.3V6M  [C_0603]  77.66 65.77 90 top
PC1241  22U_0603_6.3V6M  [C_0603]  76.87 57.09 270 bottom
PC1242  22U_0603_6.3V6M  [C_0603]  78.08 57.1 270 bottom
PC1243  22U_0603_6.3V6M  [C_0603]  86.98 61.89 90 bottom
PC1244  22U_0603_6.3V6M  [C_0603]  80.55 60.03 270 bottom
PC1245  22U_0603_6.3V6M  [C_0603]  88.21 61.89 90 bottom
PC1246  22U_0603_6.3V6M  [C_0603]  106.45 59.02 270 top
PC1247  22U_0603_6.3V6M  [C_0603]  89.28 50.44 90 top
PC1248  22U_0603_6.3V6M  [C_0603]  90.48 50.46 90 top
PC1249  22U_0603_6.3V6M  [C_0603]  90.86 58.91 90 top
PC1250  22U_0603_6.3V6M  [C_0603]  89.43 61.89 90 bottom
PC1251  22U_0603_6.3V6M  [C_0603]  110.14 55.99 180 top
PC1252  22U_0603_6.3V6M  [C_0603]  109.96 65.87 0 top
PC1253  22U_0603_6.3V6M  [C_0603]  96.29 58.57 90 top
PC1254  22U_0603_6.3V6M  [C_0603]  97.58 58.57 90 top
PC1255  22U_0603_6.3V6M  [C_0603]  90.65 61.89 90 bottom
PC1256  22U_0603_6.3V6M  [C_0603]  90.47 48.74 270 top
PC1257  22U_0603_6.3V6M  [C_0603]  93.86 54.29 270 top
PC1258  22U_0603_6.3V6M  [C_0603]  86.86 50.44 90 top
PC1259  1U_0201_6.3V6M  [C_0201]  113.29 61.73 180 top
PC1260  1U_0201_6.3V6M  [C_0201]  118.08 63.72 0 top
PC1261  1U_0201_6.3V6M  [C_0201]  117.81 50.65 0 top
PC1262  1U_0201_6.3V6M  [C_0201]  117.79 50.08 0 top
PC1263  1U_0201_6.3V6M  [C_0201]  119.33 61.95 180 top
PC1264  1U_0201_6.3V6M  [C_0201]  117.57 62.54 0 top
PC1265  1U_0201_6.3V6M  [C_0201]  118.52 56.95 180 top
PC1266  1U_0201_6.3V6M  [C_0201]  117.56 61.94 0 top
PC1267  1U_0201_6.3V6M  [C_0201]  113.31 65.23 180 top
PC1268  1U_0201_6.3V6M  [C_0201]  113.29 64.65 180 top
PC1269  1U_0201_6.3V6M  [C_0201]  118.08 64.3 0 top
PC1270  1U_0201_6.3V6M  [C_0201]  118.08 64.88 0 top
PC1271  1U_0201_6.3V6M  [C_0201]  113.29 61.14 180 top
PC1272  1U_0201_6.3V6M  [C_0201]  116.26 56.98 0 top
PC1273  1U_0201_6.3V6M  [C_0201]  113.29 62.31 180 top
PC1274  1U_0201_6.3V6M  [C_0201]  115.19 57 180 top
PC1275  1U_0201_6.3V6M  [C_0201]  119.92 54.74 0 top
PC1276  1U_0201_6.3V6M  [C_0201]  112.04 59.99 0 top
PC1277  1U_0201_6.3V6M  [C_0201]  110.24 61.93 0 top
PC1278  1U_0201_6.3V6M  [C_0201]  110.24 61.3 0 top
PC1279  1U_0201_6.3V6M  [C_0201]  109.12 60.48 180 top
PC1280  1U_0201_6.3V6M  [C_0201]  105.45 61.77 90 top
PC1281  1U_0201_6.3V6M  [C_0201]  103.65 59.91 90 top
PC1282  1U_0201_6.3V6M  [C_0201]  104.22 59.91 90 top
PC1283  1U_0201_6.3V6M  [C_0201]  104.8 59.91 90 top
PC1284  1U_0201_6.3V6M  [C_0201]  105.82 50.76 270 top
PC1285  1U_0201_6.3V6M  [C_0201]  107.05 50.18 90 top
PC1286  1U_0201_6.3V6M  [C_0201]  104.58 50.19 90 top
PC1287  1U_0201_6.3V6M  [C_0201]  112.8 50.67 270 top
PC1288  1U_0201_6.3V6M  [C_0201]  113.29 63.48 180 top
PC1289  1U_0201_6.3V6M  [C_0201]  113.29 62.9 180 top
PC1290  1U_0201_6.3V6M  [C_0201]  119.94 59.98 0 top
PC1291  1U_0201_6.3V6M  [C_0201]  119.97 59.42 0 top
PC1292  1U_0201_6.3V6M  [C_0201]  113.29 64.07 180 top
PC1293  1U_0201_6.3V6M  [C_0201]  119.97 58.86 0 top
PC1294  1U_0201_6.3V6M  [C_0201]  119.97 58.3 0 top
PC1295  1U_0201_6.3V6M  [C_0201]  119.97 57.74 0 top
PC1296  1U_0201_6.3V6M  [C_0201]  119.97 57.18 0 top
PC1297  1U_0201_6.3V6M  [C_0201]  119.15 49.49 90 top
PC1298  1U_0201_6.3V6M  [C_0201]  119.33 61.38 180 top
PC1299  1U_0201_6.3V6M  [C_0201]  118.08 63.13 0 top
PC1300  1U_0201_6.3V6M  [C_0201]  119.92 54.16 0 top
PC1301  1U_0201_6.3V6M  [C_0201]  119.92 55.3 0 top
PC1302  1U_0201_6.3V6M  [C_0201]  119.92 56.01 0 top
PC1303  1U_0201_6.3V6M  [C_0201]  119.97 56.6 0 top
PC1304  1U_0201_6.3V6M  [C_0201]  117.12 50.66 180 top
PC1305  1U_0201_6.3V6M  [C_0201]  117.13 50.08 180 top
PC1306  330_B2_2.5VM_R9M  [C_B2]  84.71 59.61 90 bottom
PC1307  330_B2_2.5VM_R9M  [C_B2]  83.24 42.56 90 bottom
PC1308  22U_0603_6.3V6M  [C_0603]  94.1 49.35 270 top
PC1309  330_B2_2.5VM_R9M  [C_B2]  77.08 66.68 270 bottom
PC1310  22U_0603_6.3V6M  [C_0603]  123.09 60.16 180 top
PC1311  22U_0603_6.3V6M  [C_0603]  58.65 54.44 0 top
PC1312  22U_0603_6.3V6M  [C_0603]  124.12 58.85 0 top
PC1313  22U_0603_6.3V6M  [C_0603]  110.4 72.54 90 top
PC1314  22U_0603_6.3V6M  [C_0603]  123.09 57.62 180 top
PC1315  22U_0603_6.3V6M  [C_0603]  58.59 58 0 top
PC1316  22U_0603_6.3V6M  [C_0603]  123.78 63.37 90 top
PC1317  22U_0603_6.3V6M  [C_0603]  111.67 72.54 90 top
PC1318  22U_0603_6.3V6M  [C_0603]  122.58 62.7 90 top
PC1319  22U_0603_6.3V6M  [C_0603]  123.09 58.89 180 top
PC1320  22U_0603_6.3V6M  [C_0603]  58.62 56.65 0 top
PC1321  22U_0603_6.3V6M  [C_0603]  123.47 53.81 0 top
PC1322  1U_0201_6.3V6M  [C_0201]  121.18 62.64 90 top
PC1323  1U_0201_6.3V6M  [C_0201]  121.86 61.68 180 top
PC1324  1U_0201_6.3V6M  [C_0201]  124.32 52.54 0 top
PC1325  1U_0201_6.3V6M  [C_0201]  123.72 52.54 180 top
PC1326  1U_0201_6.3V6M  [C_0201]  120.3 60.54 0 top
PC1327  1U_0201_6.3V6M  [C_0201]  124.11 61.81 0 top
PC1328  1U_0201_6.3V6M  [C_0201]  123.09 61.81 180 top
PC1329  330_B2_2.5VM_R9M  [C_B2]  81.49 54.48 270 bottom
PC1330  22U_0603_6.3V6M  [C_0603]  105.78 52.6 90 top
PC1331  22U_0603_6.3V6M  [C_0603]  88.07 49.16 270 top
PC1332  22U_0603_6.3V6M  [C_0603]  92.1 58.91 90 top
PC1333  22U_0603_6.3V6M  [C_0603]  86.86 49.19 270 bottom
PC1334  22U_0603_6.3V6M  [C_0603]  107.69 59.02 270 top
PC1335  22U_0603_6.3V6M  [C_0603]  110.16 57.23 180 top
PC1336  22U_0603_6.3V6M  [C_0603]  98.85 58.57 90 top
PC1337  22U_0603_6.3V6M  [C_0603]  90.48 51.86 270 bottom
PC1338  1U_0201_6.3V6M  [C_0201]  109.15 61.06 180 top
PC1339  1U_0201_6.3V6M  [C_0201]  104.81 61.77 90 top
PC1340  1U_0201_6.3V6M  [C_0201]  102.25 61.45 90 top
PC1341  1U_0201_6.3V6M  [C_0201]  111.63 50.74 270 top
PC1342  1U_0201_6.3V6M  [C_0201]  109.88 50.74 0 top
PC1343  1U_0201_6.3V6M  [C_0201]  109.27 50.73 180 top
PC1344  22U_0603_6.3V6M  [C_0603]  89.27 48.73 270 top
PC1345  22U_0603_6.3V6M  [C_0603]  92.88 49.36 270 top
PC1346  22U_0603_6.3V6M  [C_0603]  88.07 50.44 90 top
PC1347  22U_0603_6.3V6M  [C_0603]  110.14 54.74 180 top
PC1348  22U_0603_6.3V6M  [C_0603]  108.02 64.79 180 top
PC1349  22U_0603_6.3V6M  [C_0603]  107.05 52.6 90 top
PC1350  22U_0603_6.3V6M  [C_0603]  111.18 57.23 0 top
PC1351  22U_0603_6.3V6M  [C_0603]  100.48 54.45 270 top
PC1352  22U_0603_6.3V6M  [C_0603]  111.18 55.98 0 top
PC1353  22U_0603_6.3V6M  [C_0603]  91.67 48.75 270 top
PC1354  22U_0603_6.3V6M  [C_0603]  111.18 54.77 0 top
PC1355  22U_0603_6.3V6M  [C_0603]  88.07 51.84 270 bottom
PC1356  22U_0603_6.3V6M  [C_0603]  86.86 49.19 270 top
PC1357  22U_0603_6.3V6M  [C_0603]  89.27 48.73 270 bottom
PC1358  22U_0603_6.3V6M  [C_0603]  86.86 51.84 270 bottom
PC1359  22U_0603_6.3V6M  [C_0603]  88.07 49.16 270 bottom
PC1360  22U_0603_6.3V6M  [C_0603]  85.66 49.16 270 top
PC1361  22U_0603_6.3V6M  [C_0603]  85.66 49.16 270 bottom
PC1362  22U_0603_6.3V6M  [C_0603]  93.32 58.9 90 top
PC1363  1U_0201_6.3V6M  [C_0201]  109.29 50.16 180 top
PC1364  1U_0201_6.3V6M  [C_0201]  109.89 50.17 0 top
PC1365  1U_0201_6.3V6M  [C_0201]  111.06 50.73 270 top
PC1366  1U_0201_6.3V6M  [C_0201]  112.2 50.76 270 top
PC1367  1U_0201_6.3V6M  [C_0201]  109.17 61.68 180 top
PC1368  1U_0201_6.3V6M  [C_0201]  111.51 61.3 0 top
PC1369  1U_0201_6.3V6M  [C_0201]  109.17 62.31 180 top
PC1370  1U_0201_6.3V6M  [C_0201]  109.12 59.91 180 top
PC1371  1U_0201_6.3V6M  [C_0201]  111.51 61.93 0 top
PC1372  1U_0201_6.3V6M  [C_0201]  112.04 60.56 0 top
PC1373  1U_0201_6.3V6M  [C_0201]  103.04 59.3 270 top
PC1374  1U_0201_6.3V6M  [C_0201]  102.4 59.3 270 top
PC1375  1U_0201_6.3V6M  [C_0201]  105.37 59.91 90 top
PC1376  1U_0201_6.3V6M  [C_0201]  105.93 59.91 90 top
PC1377  1U_0201_6.3V6M  [C_0201]  106.49 59.91 90 top
PC1378  22U_0603_6.3V6M  [C_0603]  80.83 42.19 270 bottom
PC1379  22U_0603_6.3V6M  [C_0603]  89.28 51.84 270 bottom
PC1380  22U_0603_6.3V6M  [C_0603]  85.14 65.44 90 top
PC1381  22U_0603_6.3V6M  [C_0603]  75.65 57.09 270 top
PC1382  22U_0603_6.3V6M  [C_0603]  83.86 65.44 90 top
PC1383  22U_0603_6.3V6M  [C_0603]  81.82 60.04 270 bottom
PC1384  22U_0603_6.3V6M  [C_0603]  83.04 60.04 270 top
PC1385  22U_0603_6.3V6M  [C_0603]  84.25 60.04 270 top
PC1386  22U_0603_6.3V6M  [C_0603]  73.46 65.79 90 top
PC1387  22U_0603_6.3V6M  [C_0603]  82.61 65.44 90 bottom
PC1400  0.1U_0402_25V6  [C_0402]  164.03 51.9 0 bottom
PC1401  10U_0603_25V6M  [C_0603]  166.83 54.55 90 bottom
PC1402  10U_0603_25V6M  [C_0603]  166.85 53.59 270 bottom
PC1403  22U_0603_6.3V6M  [C_0603]  160.08 51.96 270 bottom
PC1404  22U_0603_6.3V6M  [C_0603]  158.87 51.97 270 bottom
PC1405  22U_0603_6.3V6M  [C_0603]  157.65 51.99 270 bottom
PC1406  22U_0603_6.3V6M  [C_0603]  156.06 65.49 0 bottom
PC1408  0.1U_0402_25V6  [C_0402]  165.76 54.71 90 bottom
PC1409  2200P_0402_50V7K  [C_0402]  165.81 53.25 270 bottom
PC1410  680P_0402_50V7K  [C_0402]  153.91 54.57 180 bottom
PC1411  470P_0402_50V7K  [C_0402]  164.79 58.27 90 bottom
PC1412  0.1U_0402_25V6  [C_0402]  160.78 66.95 270 bottom
PC1413  10U_0603_25V6M  [C_0603]  160.15 67.98 180 bottom
PC1414  10U_0603_25V6M  [C_0603]  161.65 69.27 0 bottom
PC1415  22U_0603_6.3V6M  [C_0603]  156.06 66.76 0 bottom
PC1416  22U_0603_6.3V6M  [C_0603]  156.06 68.05 0 bottom
PC1417  0.1U_0402_25V6  [C_0402]  161.03 70.3 0 top
PC1418  2200P_0402_50V7K  [C_0402]  161.03 70.3 0 bottom
PC1419  680P_0402_50V7K  [C_0402]  153.09 74.17 270 bottom
PC1420  470P_0402_50V7K  [C_0402]  158.42 74.02 0 bottom
PC1500  0.1U_0402_25V6  [C_0402]  56.67 36.58 90 bottom
PC1501  10U_0603_25V6M  [C_0603]  55.57 33.78 90 top
PC1502  10U_0603_25V6M  [C_0603]  55.57 33.79 90 bottom
PC1503  22U_0603_6.3V6M  [C_0603]  61.67 36.66 180 bottom
PC1504  22U_0603_6.3V6M  [C_0603]  61.67 36.66 180 top
PC1505  22U_0603_6.3V6M  [C_0603]  61.63 38.06 180 top
PC1506  22U_0603_6.3V6M  [C_0603]  72.13 36.56 180 bottom
PC1508  0.1U_0402_25V6  [C_0402]  56.72 33.77 90 top
PC1509  2200P_0402_50V7K  [C_0402]  56.72 33.77 90 bottom
PC1510  680P_0402_50V7K  [C_0402]  62.5 31.86 0 top
PC1511  470P_0402_50V7K  [C_0402]  59.33 30.75 270 bottom
PC1512  0.1U_0402_25V6  [C_0402]  66.97 36.78 90 bottom
PC1513  10U_0603_25V6M  [C_0603]  67.24 34.51 90 top
PC1514  10U_0603_25V6M  [C_0603]  67.24 34.51 90 bottom
PC1515  22U_0603_6.3V6M  [C_0603]  73.46 36.18 90 bottom
PC1516  22U_0603_6.3V6M  [C_0603]  72.13 36.56 180 top
PC1517  0.1U_0402_25V6  [C_0402]  66.13 34.67 90 top
PC1518  2200P_0402_50V7K  [C_0402]  66.13 34.67 90 bottom
PC1519  680P_0402_50V7K  [C_0402]  72.15 34.4 180 top
PC1520  470P_0402_50V7K  [C_0402]  68.67 30.27 270 bottom
PC1529  330_B2_2.5VM_R9M  [C_B2]  80.3 65.7 270 bottom
PD103  -  [RB751V-40_SOD323-2]  33.51 2.49 180 bottom
PD104  -  [TVNST52302AB0_SOT523-3]  98.62 10.74 0 top
PD105  -  [TVNST52302AB0_SOT523-3]  101.35 10.74 0 top
PD106  -  [RB751V-40_SOD323-2]  33.57 4.29 180 bottom
PD107  -  [RB751V-40_SOD323-2]  33.57 5.94 180 bottom
PD108  -  [SE30AFB-M3-6A_SMA2]  40.05 11.3 90 bottom
PD109  -  [SE30AFB-M3-6A_SMA2]  46.99 11.25 90 bottom
PD110  -  [SE30AFB-M3-6A_SMA2]  184.96 3.03 0 bottom
PD111  -  [RB751V-40_SOD323-2]  33.58 7.79 180 bottom
PD300  -  [RB751V-40_SOD323-2]  55.65 8.77 270 bottom
PD301  -  [RB751V-40_SOD323-2]  57.29 8.35 270 bottom
PD305  -  [BAT54CW_SOT323-3]  61.34 4.38 90 bottom
PD306  -  [BAT54CW_SOT323-3]  62.93 4.38 270 bottom
PH1000  470K_0402_5%_ TSM0B474J4702RE  [R_0402]  70.74 44.93 90 bottom
PH1001  10K_0402_5%_B25/50 4250K  [R_0402]  54.73 58.88 180 bottom
PH1002  10K_0402_5%_B25/50 4250K  [R_0402]  71.35 37.93 0 bottom
PH1003  10K_0402_5%_B25/50 4250K  [R_0402]  68.09 64.1 90 bottom
PH1004  470K_0402_5%_ TSM0B474J4702RE  [R_0402]  70.03 57.37 180 bottom
PJP500  -  [JUMP_43X118]  50.36 38.55 90 bottom
PJP501  -  [JUMP_43X118]  43.6 38.95 90 bottom
PJP600  -  [JUMP_43X118]  129.26 12.28 0 bottom
PJP601  -  [JUMP_43X39]  119.51 11.91 90 bottom
PJP700  -  [JUMP_43X79]  143.22 11.96 0 bottom
PJP800  -  [JUMP_43X39]  152.91 57.94 270 bottom
PJP900  -  [JUMP_43X39]  154.8 12.47 90 bottom
PJP1400  -  [JUMP_43X79]  155.88 52.16 180 bottom
PJP1401  -  [JUMP_43X79]  153.37 66.83 270 bottom
PL100  HCB2012KF-121T50_0805  [TAI-T_HCB2012KF-121T50_2P]  35.22 20.61 0 bottom
PL101  HCB2012KF-121T50_0805  [TAI-T_HCB2012KF-121T50_2P]  44.67 20.24 180 bottom
PL102  HCB2012KF-121T50_0805  [TAI-T_HCB2012KF-121T50_2P]  87.99 12.95 90 bottom
PL103  HCB2012KF-121T50_0805  [TAI-T_HCB2012KF-121T50_2P]  87.79 10.81 180 bottom
PL104  HCB2012KF-121T50_0805  [TAI-T_HCB2012KF-121T50_2P]  199.69 6.51 180 bottom
PL105  HCB2012KF-121T50_0805  [TAI-T_HCB2012KF-121T50_2P]  87.78 9.02 180 bottom
PL301  2.2UH_MHCB06030-2R2M-C1L_10A_20%  [CHILI_MHCB06030-2R2M-C1L_2P]  65.23 25.31 0 bottom
PL302  1UH_MMD-04BZ-1R0M-V1_3.75A_20%  [MAG_MMD-04BZ-1R0M-V1_2P]  57.59 14.27 90 bottom
PL500  HCB2012KF-121T50_0805  [TAI-T_HCB2012KF-121T50_2P]  51.11 21.34 0 bottom
PL501  1.5UH_MMD-05CZN1R5M-V1L_7.2A_20%  [MAG_MMD-05CZN1R5M-V1L_2P]  50.87 31.06 90 bottom
PL502  HCB2012KF-121T50_0805  [TAI-T_HCB2012KF-121T50_2P]  45.49 23.62 90 top
PL503  HCB2012KF-121T50_0805  [TAI-T_HCB2012KF-121T50_2P]  45.49 23.62 90 bottom
PL504  1.5UH_PCMC063T-1R5MN_9A_20%  [CYNTE_PCMC063T-1R5MN_2P]  43.07 29.87 90 bottom
PL600  HCB2012KF-121T50_0805  [TAI-T_HCB2012KF-121T50_2P]  112.65 5.21 0 bottom
PL601  1UH_MMD-05CZ-1R0M-M7L_7A_20%  [L_5X5X3_M_2P]  122.9 6.32 0 bottom
PL700  HCB2012KF-121T50_0805  [TAI-T_HCB2012KF-121T50_2P]  129.85 2.55 0 bottom
PL701  1UH_MMD-05CZ-1R0M-M7L_7A_20%  [L_5X5X3_M_2P]  140.64 2.89 90 bottom
PL800  HCB1608KF-121T30_0603  [TAI-T_HCB1608KF-121T3_L0603_2P]  168.79 61.69 180 bottom
PL801  2.2UH_HEI322512A-2R2M-Q8_2.7A_20%  [CHILI_HEI322512A-2R2M-Q8_2P]  155.61 61.86 270 bottom
PL900  HCB1608KF-121T30_0603  [TAI-T_HCB1608KF-121T3_L0603_2P]  159.03 2.72 180 bottom
PL901  2.2UH_HEI322512A-2R2M-Q8_2.7A_20%  [CHILI_HEI322512A-2R2M-Q8_2P]  156.71 10.09 180 bottom
PL1100  0.15UH_HPPC06030-R15M-Q8_35A_20%  [CHILI_MHCB06030-2R2M-C1L_2P]  70.45 61.36 0 bottom
PL1101  HCB2012KF-121T50_0805  [TAI-T_HCB2012KF-121T50_2P]  54.28 39.43 0 bottom
PL1102  HCB2012KF-121T50_0805  [TAI-T_HCB2012KF-121T50_2P]  54.28 41.22 0 bottom
PL1103  0.15UH_HPPC06030-R15M-Q8_35A_20%  [NEC_MPCH0730LR15_2P]  72.61 49.31 90 bottom
PL1106  HCB2012KF-121T50_0805  [TAI-T_HCB2012KF-121T50_2P]  54.28 43.1 0 bottom
PL1107  0.15UH_HPPC06030-R15M-Q8_35A_20%  [NEC_MPCH0730LR15_2P]  72.61 49.31 0 bottom
PL1108  HCB2012KF-121T50_0805  [TAI-T_HCB2012KF-121T50_2P]  51.44 44.69 90 bottom
PL1150  0.15UH_HPPC06030-R15M-Q8_35A_20%  [CHILI_MHCB06030-2R2M-C1L_2P]  72.05 41.94 0 bottom
PL1151  0.47UH_MMD05CZR47M_12A_20%  [CYNTE_PCMB053T-R47MS_2P]  54.95 55.8 0 bottom
PL1400  HCB1608KF-121T30_0603  [TAI-T_HCB1608KF-121T3_L0603_2P]  169.89 54.38 180 bottom
PL1401  1UH_HEI322512A-1R0M-Q8_3.7A_20%  [CHILI_HEI322512A-2R2M-Q8_2P]  158.62 56.16 270 bottom
PL1402  HCB1608KF-121T30_0603  [TAI-T_HCB1608KF-121T3_L0603_2P]  163.02 68.03 180 bottom
PL1403  1UH_HEI322512A-1R0M-Q8_3.7A_20%  [CHILI_HEI322512A-2R2M-Q8_2P]  153.99 71.64 270 bottom
PL1500  HCB1608KF-121T30_0603  [TAI-T_HCB1608KF-121T3_L0603_2P]  56.47 30.14 90 bottom
PL1501  1UH_HEI322512A-1R0M-Q8_3.7A_20%  [CHILI_HEI322512A-2R2M-Q8_2P]  63.62 32.34 90 bottom
PL1502  HCB1608KF-121T30_0603  [TAI-T_HCB1608KF-121T3_L0603_2P]  66.12 31.6 90 bottom
PL1503  1UH_HEI322512A-1R0M-Q8_3.7A_20%  [CHILI_HEI322512A-2R2M-Q8_2P]  74.4 31.82 90 bottom
PQ100  -  [AON7405_DFN8-5]  35.64 18.56 0 bottom
PQ101  -  [AON7405_DFN8-5]  37.53 10.83 180 bottom
PQ104  S TR AO7401 1P SC70-3  [SI1303DL-T1-E3_SOT323-3]  35.95 6.37 180 bottom
PQ106  -  [L2N7002WT1G_SC70-3]  33.87 19.64 270 bottom
PQ108  -  [L2N7002WT1G_SC70-3]  32.6 9.29 180 bottom
PQ109  -  [DMN66D0LDW-7_SOT363-6]  40 8.2 270 bottom
PQ113  -  [AON7405_DFN8-5]  42.47 18.44 0 bottom
PQ114  -  [AON7405_DFN8-5]  44.45 10.88 180 bottom
PQ115  S TR AO7401 1P SC70-3  [SI1303DL-T1-E3_SOT323-3]  48.15 8.13 270 top
PQ117  -  [DMN66D0LDW-7_SOT363-6]  66.22 8.12 0 bottom
PQ118  -  [L2N7002WT1G_SC70-3]  51.27 15.34 270 bottom
PQ119  -  [L2N7002WT1G_SC70-3]  42.29 8.11 0 bottom
PQ120  -  [DMN66D0LDW-7_SOT363-6]  60.8 8.1 0 bottom
PQ121  -  [DMN66D0LDW-7_SOT363-6]  47.09 6.15 270 bottom
PQ122  -  [DMN66D0LDW-7_SOT363-6]  52.71 16.21 90 bottom
PQ123  S TR AO7401 1P SC70-3  [SI1303DL-T1-E3_SOT323-3]  44.73 2.92 90 bottom
PQ124  S TR AO7401 1P SC70-3  [SI1303DL-T1-E3_SOT323-3]  48.58 4.23 0 bottom
PQ125  -  [DMN66D0LDW-7_SOT363-6]  52.92 3.24 270 bottom
PQ126  -  [DMN65D8LW-7_SOT323-3]  41.07 3.7 270 bottom
PQ127  -  [DMN66D0LDW-7_SOT363-6]  52.71 13.78 90 bottom
PQ128  -  [DMN66D0LDW-7_SOT363-6]  63.3 8.07 0 bottom
